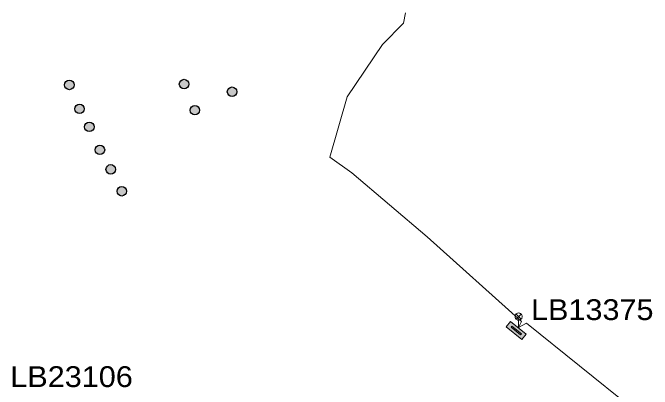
# Model space of a CAD drawing. Extents: x -688091 to -687952, y -973692 to -973558.
# Drawn here: x -688029.4 to -687962.8, y -973617.3 to -973578.1 of the extents above; entities that cross this region are included whole.
import ezdxf

# ---------------------------------------------------------------- set-up
doc = ezdxf.new("R2010")
doc.units = 0
doc.header["$LTSCALE"] = 0.87
doc.layers.add('1', color=7, linetype='Continuous', lineweight=13)

msp = doc.modelspace()

# ---------------------------------------------------------------- hatches: boundary and pattern name
at = {"layer": '1'}
for points in [[(-688023.3994, -973586.0746, 1), (-688023.6982, -973585.1303, 1)], [(-688011.4458, -973585.9815, 1), (-688011.7446, -973585.0372, 1)], [(-688006.4443, -973586.7809, 1), (-688006.7431, -973585.8366, 1)], [(-688022.3381, -973588.5685, 1), (-688022.6369, -973587.6242, 1)], [(-688010.3185, -973588.7064, 1), (-688010.6173, -973587.7621, 1)], [(-688021.3153, -973590.4426, 1), (-688021.6142, -973589.4984, 1)], [(-688020.2139, -973592.845, 1), (-688020.5128, -973591.9008, 1)], [(-688019.0867, -973594.8725, 1), (-688019.3855, -973593.9282, 1)], [(-688017.9328, -973597.155, 1), (-688018.2317, -973596.2108, 1)], [(-687977.573, -973610.263), (-687975.942, -973611.586), (-687976.382, -973612.13), (-687978.014, -973610.807)], [(-687977.573, -973610.263), (-687975.942, -973611.586), (-687976.382, -973612.13), (-687978.014, -973610.807)], [(-687977.423, -973610.745), (-687976.444, -973611.539), (-687976.532, -973611.648), (-687977.511, -973610.854)], [(-687977.423, -973610.745), (-687976.444, -973611.539), (-687976.532, -973611.648), (-687977.511, -973610.854)]]:
    msp.add_hatch(color=256, dxfattribs=at).paths.add_polyline_path(points)

# ---------------------------------------------------------------- linework, layer by layer
for p, q in [((-687976.995, -973609.475), (-687976.465, -973610.005)), ((-687976.995, -973610.005), (-687976.465, -973609.475)), ((-687976.995, -973609.475), (-687976.465, -973610.005)), ((-687976.995, -973610.005), (-687976.465, -973609.475)), ((-687976.73, -973610.89), (-687976.73, -973610.115)), ((-687976.73, -973610.89), (-687976.73, -973610.115))]:
    msp.add_line(p, q, dxfattribs=at)
for points in [[(-687976.73, -973610.89), (-687976.428, -973610.261), (-687986.244, -973601.439), (-687994.097, -973594.745), (-687996.394, -973593.145), (-687994.602, -973586.833), (-687990.909, -973581.38), (-687988.719, -973579.15), (-687988.525, -973578.081)], [(-687968.17, -973629.15), (-687967.313, -973628.479), (-687963.291, -973622.435), (-687964.867, -973619.32), (-687975.911, -973610.419), (-687976.73, -973610.89)]]:
    msp.add_lwpolyline(points, dxfattribs=at)
for points in [[(-687976.355, -973609.74), (-687976.361, -973609.675), (-687976.378, -973609.612), (-687976.405, -973609.552), (-687976.443, -973609.499), (-687976.489, -973609.453), (-687976.542, -973609.415), (-687976.602, -973609.388), (-687976.665, -973609.371), (-687976.73, -973609.365), (-687976.795, -973609.371), (-687976.858, -973609.388), (-687976.918, -973609.415), (-687976.971, -973609.453), (-687977.017, -973609.499), (-687977.055, -973609.552), (-687977.082, -973609.612), (-687977.099, -973609.675), (-687977.105, -973609.74), (-687977.099, -973609.805), (-687977.082, -973609.868), (-687977.055, -973609.928), (-687977.017, -973609.981), (-687976.971, -973610.027), (-687976.918, -973610.065), (-687976.858, -973610.092), (-687976.795, -973610.109), (-687976.73, -973610.115), (-687976.665, -973610.109), (-687976.602, -973610.092), (-687976.542, -973610.065), (-687976.489, -973610.027), (-687976.443, -973609.981), (-687976.405, -973609.928), (-687976.378, -973609.868), (-687976.361, -973609.805)], [(-687976.355, -973609.74), (-687976.361, -973609.675), (-687976.378, -973609.612), (-687976.405, -973609.552), (-687976.443, -973609.499), (-687976.489, -973609.453), (-687976.542, -973609.415), (-687976.602, -973609.388), (-687976.665, -973609.371), (-687976.73, -973609.365), (-687976.795, -973609.371), (-687976.858, -973609.388), (-687976.918, -973609.415), (-687976.971, -973609.453), (-687977.017, -973609.499), (-687977.055, -973609.552), (-687977.082, -973609.612), (-687977.099, -973609.675), (-687977.105, -973609.74), (-687977.099, -973609.805), (-687977.082, -973609.868), (-687977.055, -973609.928), (-687977.017, -973609.981), (-687976.971, -973610.027), (-687976.918, -973610.065), (-687976.858, -973610.092), (-687976.795, -973610.109), (-687976.73, -973610.115), (-687976.665, -973610.109), (-687976.602, -973610.092), (-687976.542, -973610.065), (-687976.489, -973610.027), (-687976.443, -973609.981), (-687976.405, -973609.928), (-687976.378, -973609.868), (-687976.361, -973609.805)], [(-687977.573, -973610.263), (-687975.942, -973611.586), (-687976.382, -973612.13), (-687978.014, -973610.807)], [(-687977.573, -973610.263), (-687975.942, -973611.586), (-687976.382, -973612.13), (-687978.014, -973610.807)], [(-687977.573, -973610.263), (-687975.942, -973611.586), (-687976.382, -973612.13), (-687978.014, -973610.807)], [(-687977.573, -973610.263), (-687975.942, -973611.586), (-687976.382, -973612.13), (-687978.014, -973610.807)], [(-687977.423, -973610.745), (-687976.444, -973611.539), (-687976.532, -973611.648), (-687977.511, -973610.854)], [(-687977.423, -973610.745), (-687976.444, -973611.539), (-687976.532, -973611.648), (-687977.511, -973610.854)]]:
    msp.add_lwpolyline(points, close=True, dxfattribs=at)
at = {"layer": '1', "lineweight": 25}
for centre in [(-688023.5488, -973585.6025), (-688011.5952, -973585.5094), (-688006.5937, -973586.3088), (-688022.4875, -973588.0964), (-688010.4679, -973588.2343), (-688021.4648, -973589.9705), (-688020.3634, -973592.3729), (-688019.2361, -973594.4004), (-688018.0823, -973596.6829)]:
    msp.add_circle(centre, 0.4952, dxfattribs=at)

# ---------------------------------------------------------------- texts
at = {"layer": '1', "width": 1.1}
for s, height, p in [('LB13375', 2.167, (-687975.435, -973610.106)), ('LB23106', 2.168, (-688029.706, -973617.088))]:
    msp.add_text(s, height=height, dxfattribs=at).set_placement(p)

doc.saveas('drawing.dxf')
